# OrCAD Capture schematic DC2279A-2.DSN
size Custom; title: 800mA SINGLE RESISTOR; rev: 2; note: DC2279A
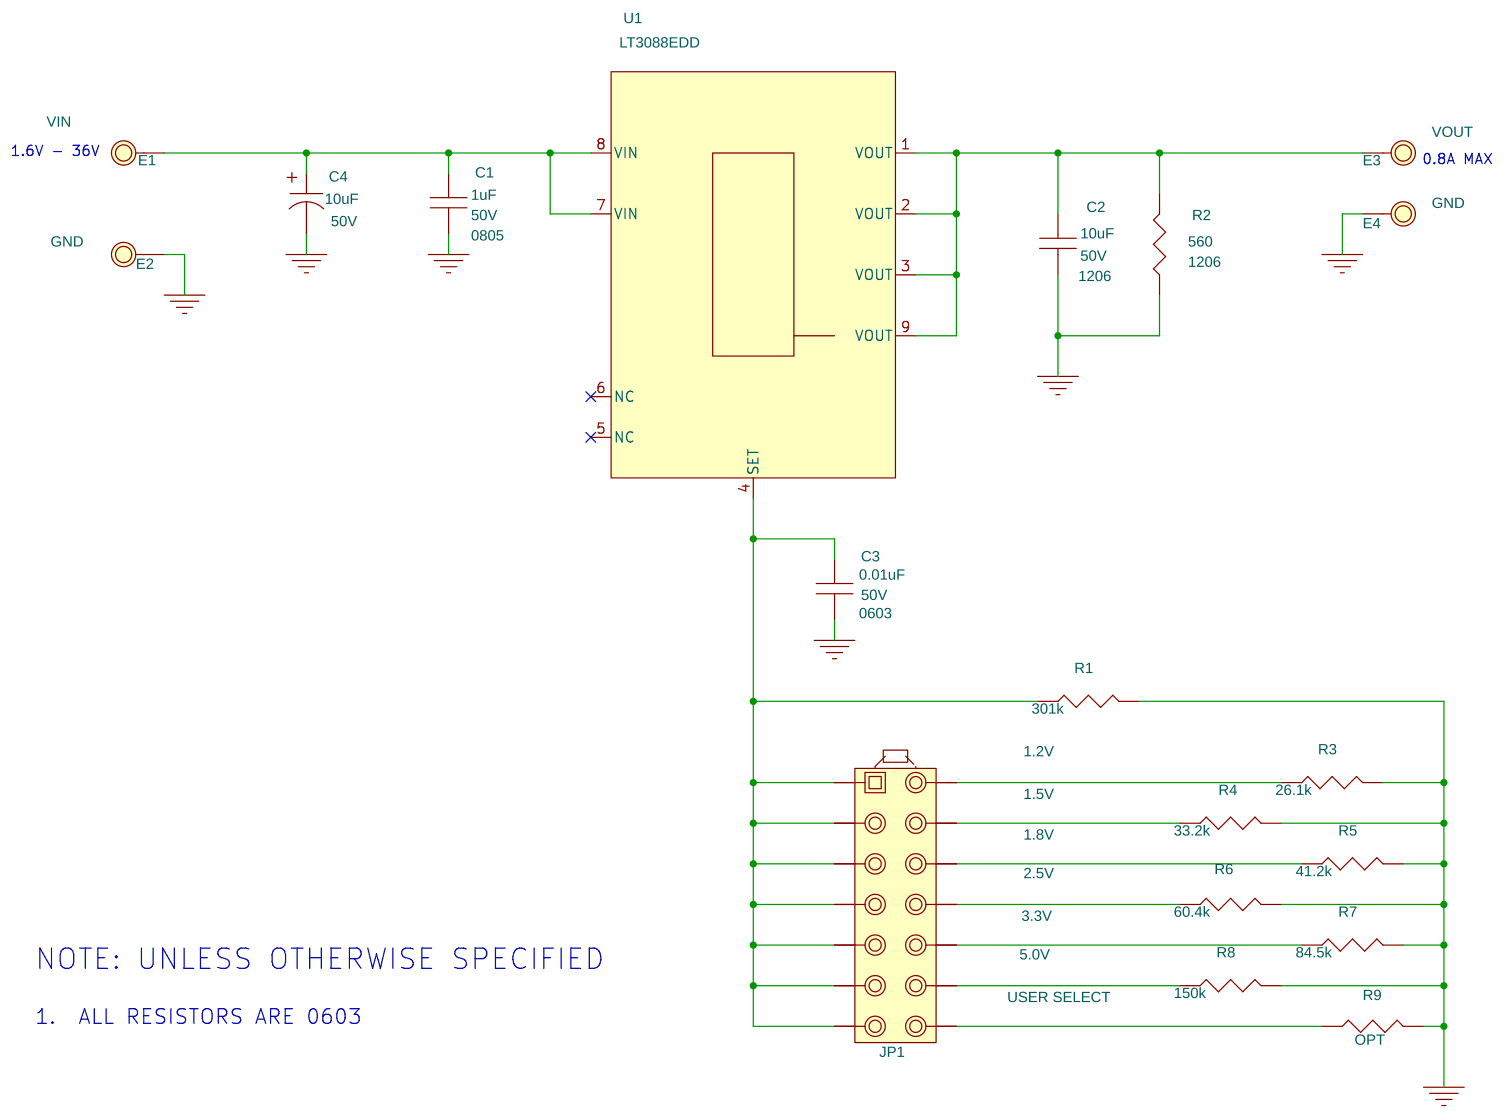
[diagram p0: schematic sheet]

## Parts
C1  1uF  [0805]
C2  10uF  [1206]
C3  0.01uF  [0603]
C4  10uF  [CAP-CE-5X5.4]
E1  Testpoint  [MM/2501]
E2  Testpoint  [MM/2501]
E3  Testpoint  [MM/2501]
E4  Testpoint  [MM/2501]
JP1  2 x 7 (2mm Ctrs.)  [JP7X2/079]
R1  301k  [0603]
R2  560  [1206]
R3  26.1k  [0603]
R4  33.2k  [0603]
R5  41.2k  [0603]
R6  60.4k  [0603]
R7  84.5k  [0603]
R8  150k  [0603]
R9  OPT  [0603]
U1  LT3088EDD  [DFN-8(3X3)]
XJP1  2mm Ctrs.

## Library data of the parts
C1 C3 = CAP_NP: 1ST PART FIELD: 50V; Value1: 50V
C2 = CAP_NP: Value1: 50V
C4 = CAP+_0: 1ST PART FIELD: 50V; VALUE2: 50V
E1 = MillMax-2501-2: V: VIN
E2 E4 = MillMax-2501-2: V: GND
E3 = MillMax-2501-2: V: VOUT
JP1 = Samtec_TMM-107-02-L-D: 10th Part Field: 1.2V; 11th Part Field: 1.5V; 12th Part Field: 1.8V; 13tht Part Field: 2.5V; 14th Part Field: 3.3V; 15th Part Field: 5.0V; 16th Part Field: USER SELECT
R1-R3 = CRCW060324K3FKEA
R4 = CRCW060330K1FKEA
R5 = CRCW060336K5FKED
R6 = CRCW060349K9FKEA
R7 = CRCW060366K5FKEA
R8 = CRCW0603100KFKEA
R9 = RES0603
U1 = LT3088EDD_0
XJP1 = Samtec_2SN-BK-G

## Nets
GND: C1.2 C2.2 C3.2 C4.2 E2.1 E4.1 R1.2 R2.1 R3.2 R4.2 R5.2 R6.2 R7.2 R8.2 R9.2
N16828724: C1.1 C4.1 E1.1 U1.7(VIN) U1.8(VIN)
N16833411: C2.1 E3.1 R2.2 U1.1(VOUT) U1.2(VOUT) U1.3(VOUT) U1.9(VOUT)
N16836902: JP1.2 R3.1
N16836904: JP1.4 R4.1
N16836906: JP1.6 R5.1
N16836908: JP1.8 R6.1
N16836910: JP1.10 R7.1
N16836914: JP1.12 R8.1
N16836918: JP1.14 R9.1
N16840260: C3.1 JP1.1 JP1.3 JP1.5 JP1.7 JP1.9 JP1.11 JP1.13 R1.1 U1.4(SET)

Not connected (* = marked no-connect by the designer): U1 5(NC)* 6(NC)*

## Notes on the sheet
- 1.6V - 36V
- 0.8A MAX
- NOTE: UNLESS OTHERWISE SPECIFIED
- 1.  ALL RESISTORS ARE 0603
